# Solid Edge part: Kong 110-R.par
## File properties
Title: Kong 110/R 106x49 Cm
Author: DESYS
Template: Normal.par
Last saved by: s.pallini
Revision: 21
Application: Solid Edge
Tipo di contenuto documento: 0
Precisione: 0,990
Document Number: 8054/R
Revision: 0
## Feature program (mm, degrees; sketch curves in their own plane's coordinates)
thicken "Assegnare_spessore_2"  Distance1 = 10 mm
thicken "Assegnare_spessore_1"  Distance1 = 10 mm
fillet "Rotondo_1" radius 30
fillet "Rotondo_2" radius 5
fillet "Rotondo_3" radius 5
sketch for "unnamed Cutout 1" plane through (0, 0, 0) normal (0, 0, 1) x-axis (1, 0, 0)
  circle centre (0, 0) radius 25
extrude "unnamed Cutout 1" cut through
sketch for "unnamed Protrusion 1" plane through (0, 0, 0) normal (0, 0, 1) x-axis (1, 0, 0)
extrude "unnamed Protrusion 1" add
fillet "Rotondo_4" radius 10
sketch for "ExtrudedCutout_2" #1 plane through (0.4335, 0, 0) normal (0, 0, -1) x-axis (0, -1, 0)
sketch for "ExtrudedCutout_2" #2 plane through (0.4335, 0, 0) normal (0, 0, -1) x-axis (0, -1, 0)
sketch for "ExtrudedCutout_2" #3 plane through (0.4335, 0, 0) normal (0, 0, -1) x-axis (0, -1, 0)
extrude "ExtrudedCutout_2" cut finite 10 along -normal
fillet "Rotondo_5" radius 5
sketch for "ExtrudedProtrusion_2" plane through (-0.1376, 0, 150) normal (0, 0, -1) x-axis (-1, 0, 0)
extrude "ExtrudedProtrusion_2" add through along +normal  Profile_Plane1_Distance = 150 mm
draft "Draft_1"  Angles1 = 10 deg
sketch for "Foro_1" plane through (0, 0, 0) normal (0, 0, 1) x-axis (1, 0, 0)
  hole centre (170, 0) bore radius 17.5
  dimension (linear) = 170
hole "Foro_1" diameter 35 through
sketch for "ExtrudedCutout_3" plane through (-0.1376, 0, 0) normal (0, 0, -1) x-axis (-1, 0, 0)
  circle centre (-176.1376, 0) radius 42.5
extrude "ExtrudedCutout_3" cut finite 145 along -normal
fillet "Rotondo_6" radius 8
fillet "Rotondo_7" radius 3
fillet "Rotondo_8" radius 8
Other named dimensions: "CurveByTable_2": Tolerance = 1 mm | "CurveByTable_3": Tolerance = 1 mm | "CurveByTable_4": Tolerance = 1 mm
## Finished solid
Body 1: solid body, 49 faces, 91 edges, 44 vertices.
  Faces by surface: blend 28, plane 7, cylinder 6, torus 3, swept 2, cone 1, offset 1, spline 1
  Edges by curve: intersection 49, circle 35, line 6, ellipse 1
Body 2: sheet body, 1 face, 4 edges, 4 vertices.
  Faces by surface: spline 1
  Edges by curve: spline 4
Bounding box of the edges (mm; curved faces can reach further): 423.983 x 1110.000 x 169.262, from (-180.028, -580, 0) to (243.9553, 530, 169.2616).
Cylindrical faces by radius (mm): R8 x2, R17.5 x1, R25 x1, R35 x1, R42.5 x1
Conical faces (half-angle, radius in mm at the cone's reference point): 10 deg R122 x1
Toroidal faces (ring radius, tube radius in mm): R20.5 r3 x1, R30 r5 x1, R115.2872 r8 x1
Planar faces by outward normal: +z 1, -z 4, oblique 2
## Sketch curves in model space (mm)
arc centre (2.6148, 0, 257.8149) radius 254.8849 from (-180, 0, 80) through (53.1737, 0, 7.9947) to (240, 0, 165)
circle centre (0, 0, 20) radius 25
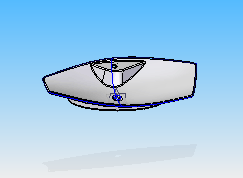
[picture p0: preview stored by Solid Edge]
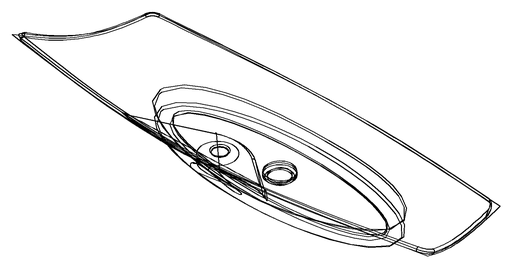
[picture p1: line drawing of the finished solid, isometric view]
